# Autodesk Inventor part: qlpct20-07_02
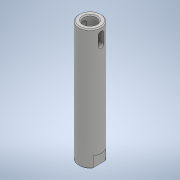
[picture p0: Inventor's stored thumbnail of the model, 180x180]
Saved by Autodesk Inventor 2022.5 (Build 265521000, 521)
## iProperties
Part Number: qlpct20-07_02
Material: 一般
Document SubType Name: Modeling
Designer: ImaoCorp
Density: 1 g/cm^3
Appearance: 既定
Author: ImaoCorp
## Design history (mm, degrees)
feature "qlpct20-07_02"
node "ソリッド1"
